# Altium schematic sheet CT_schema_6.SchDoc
size 356 x 184 mm
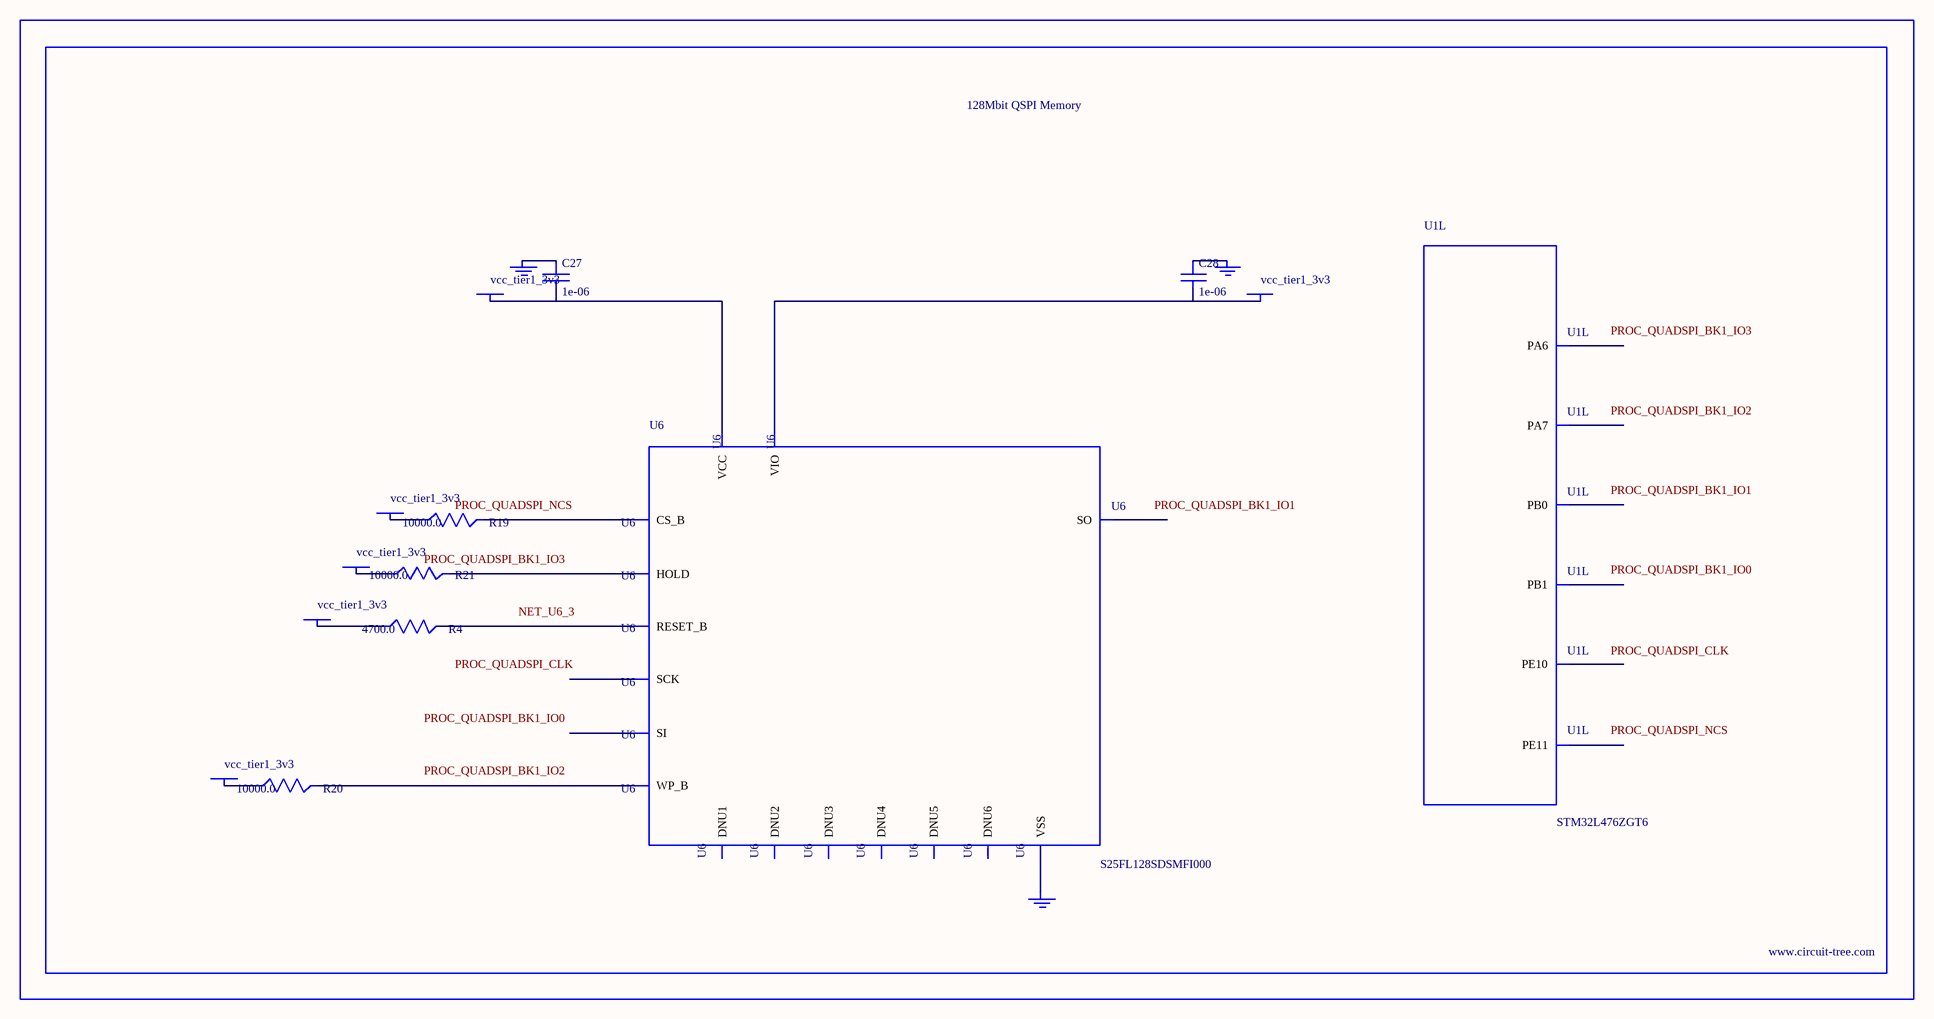
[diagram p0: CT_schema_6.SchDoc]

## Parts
BORDER5  (no value)
C27  1e-06  [C0603]
C28  1e-06  [C0603]
GND_INSTANCE_5_0  (no value)
GND_INSTANCE_5_1  (no value)
GND_INSTANCE_5_2  (no value)
POWER_INSTANCE_5_0  vcc_tier1_3v3
POWER_INSTANCE_5_1  vcc_tier1_3v3
POWER_INSTANCE_5_2  vcc_tier1_3v3
POWER_INSTANCE_5_3  vcc_tier1_3v3
POWER_INSTANCE_5_4  vcc_tier1_3v3
POWER_INSTANCE_5_5  vcc_tier1_3v3
R4  4700.0  [R0603]
R19  10000.0  [R0603]
R20  10000.0  [R0603]
R21  10000.0  [R0603]
U1  STM32L476ZGT6  [LQFP144]  (part L of 13)
U6  S25FL128SDSMFI000  [S25FL128SDSMFI000]

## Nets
NetC27_1: C27.1 GND_INSTANCE_5_0.0(GND)
NetC27_2: C27.2 POWER_INSTANCE_5_1.0(PWR) U6.2(VCC)
NetC28_1: C28.1 GND_INSTANCE_5_1.0(GND)
NetC28_2: C28.2 POWER_INSTANCE_5_4.0(PWR) U6.14(VIO)
NetGND_INSTANCE_5_2_0: GND_INSTANCE_5_2.0(GND) U6.10(VSS)
NetPOWER_INSTANCE_5_0_0: POWER_INSTANCE_5_0.0(PWR) R21.1
NetPOWER_INSTANCE_5_2_0: POWER_INSTANCE_5_2.0(PWR) R19.1
NetPOWER_INSTANCE_5_3_0: POWER_INSTANCE_5_3.0(PWR) R20.1
NetPOWER_INSTANCE_5_5_0: POWER_INSTANCE_5_5.0(PWR) R4.1
NetR4_2: R4.2 U6.3(RESET_B)
NetR19_2: R19.2 U6.7(CS_B)
NetR20_2: R20.2 U6.9(WP_B)
NetR21_2: R21.2 U6.1(HOLD)

Not connected (* = marked no-connect by the designer): U1 42(PA6) 43(PA7) 46(PB0) 47(PB1) 63(PE10) 64(PE11); U6 4(DNU1) 5(DNU2) 6(DNU6) 8(SO) 11(DNU3) 12(DNU4) 13(DNU5) 15(SI) 16(SCK)

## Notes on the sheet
- Labels drawn without touching a wire or pin: NET_U6_3, PROC_QUADSPI_BK1_IO0, PROC_QUADSPI_BK1_IO1, PROC_QUADSPI_BK1_IO2, PROC_QUADSPI_BK1_IO3, PROC_QUADSPI_CLK, PROC_QUADSPI_NCS

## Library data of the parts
BORDER5 = BORDER_PAGE5
C27 C28 = C0603C105K3RACTU
GND_INSTANCE_5_0-GND_INSTANCE_5_2 = GND
POWER_INSTANCE_5_0-POWER_INSTANCE_5_5 = PWR
R4 = RC0603JR-074K7L
R19-R21 = RC0603JR-0710KL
